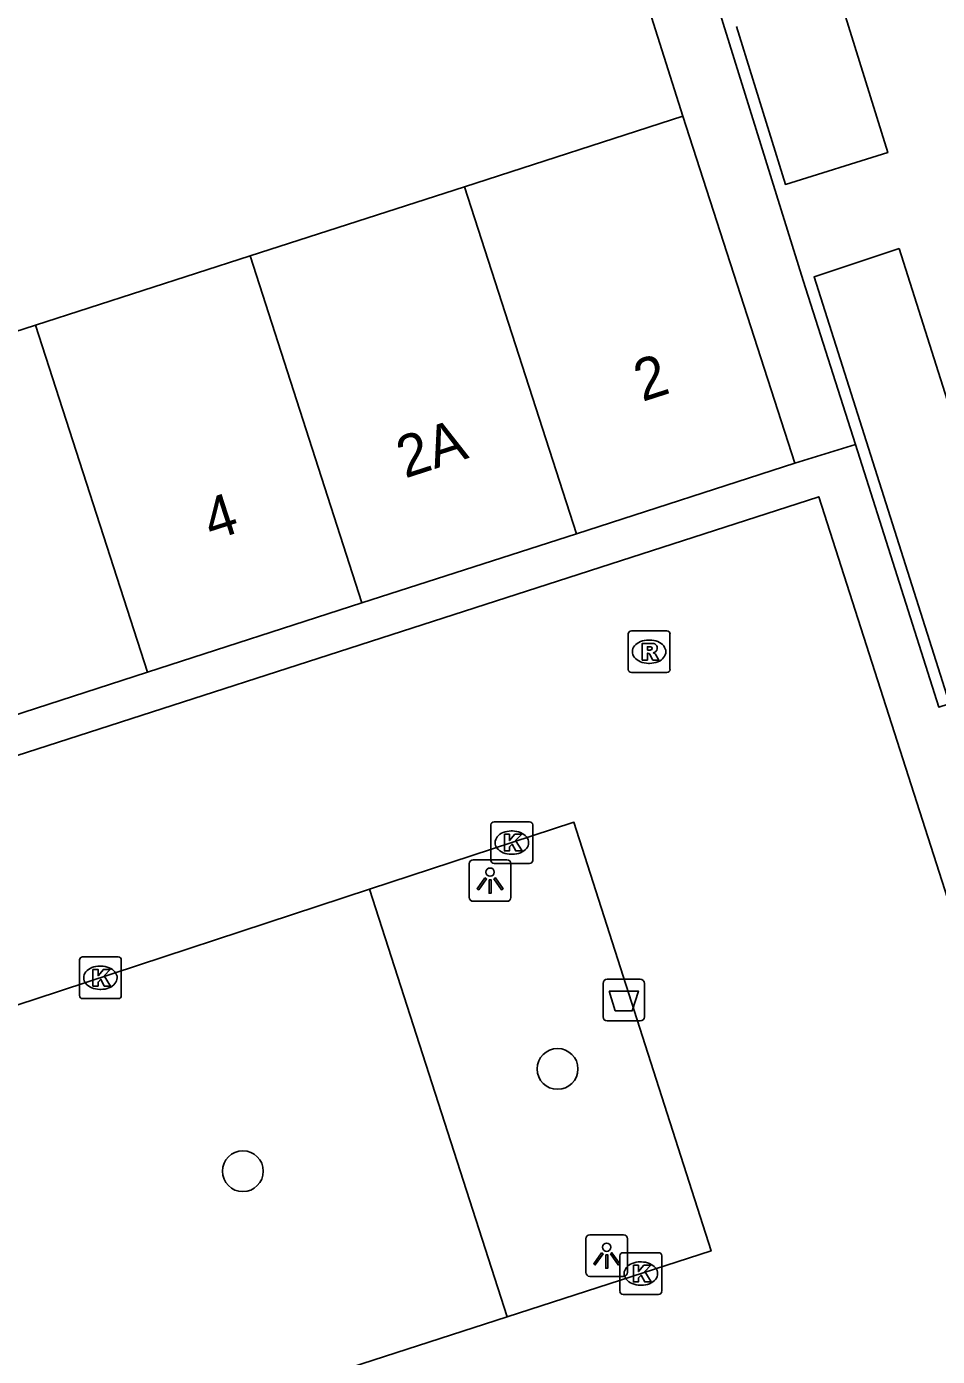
# Model space of a CAD drawing. Extents: x 159377 to 159983, y 382996 to 383595.
# Drawn here: x 159683.95 to 159705.78, y 383204.43 to 383236.31 of the extents above; entities that cross this region are included whole.
import ezdxf

# ---------------------------------------------------------------- set-up
doc = ezdxf.new("R2010")
doc.units = 0
for name, color, linetype in [('IMGEO_Afvalbak', 7, 'Continuous'), ('IMGEO_Boom', 7, 'Continuous'), ('IMGEO_Kolk', 7, 'Continuous'), ('IMGEO_Lichtpunt', 7, 'Continuous'), ('IMGEO_Pand', 7, 'Continuous'), ('IMGEO_Pand_nummerreeks', 7, 'Continuous'), ('IMGEO_Rijbaan_lokaal_open', 7, 'Continuous'), ('IMGEO_Rioolput', 7, 'Continuous'), ('IMGEO_Voetpad_open', 7, 'Continuous')]:
    doc.layers.add(name, color=color, linetype=linetype)

msp = doc.modelspace()

# ---------------------------------------------------------------- linework, layer by layer
at = {"layer": 'IMGEO_Afvalbak'}
for p, q in [((159697.768, 383212.573), (159697.768, 383213.373)), ((159697.768, 383213.373), (159697.768, 383212.573)), ((159697.868, 383213.473), (159698.658, 383213.473)), ((159698.658, 383213.473), (159697.868, 383213.473)), ((159698.758, 383213.373), (159698.758, 383212.573)), ((159698.758, 383212.573), (159698.758, 383213.373)), ((159698.658, 383212.473), (159697.868, 383212.473)), ((159697.868, 383212.473), (159698.658, 383212.473))]:
    msp.add_line(p, q, dxfattribs=at)
msp.add_lwpolyline([(159697.911, 383213.187), (159698.615, 383213.187), (159698.466, 383212.717), (159698.06, 383212.717), (159697.911, 383213.187)], dxfattribs=at)
for centre, start, end in [((159697.868, 383213.373), 90, 180), ((159697.868, 383213.373), 90, 180), ((159698.658, 383213.373), 0, 90), ((159698.658, 383213.373), 360, 90), ((159697.868, 383212.573), 180, 270), ((159697.868, 383212.573), 180, 270), ((159698.658, 383212.573), 270, 0), ((159698.658, 383212.573), 270, 0)]:
    msp.add_arc(centre, 0.1, start, end, dxfattribs=at)
at = {"layer": 'IMGEO_Boom'}
for centre in [(159696.677, 383211.322), (159689.133, 383208.87)]:
    msp.add_circle(centre, 0.489, dxfattribs=at)
at = {"layer": 'IMGEO_Kolk'}
for p, q in [((159695.08, 383216.322), (159695.08, 383217.174)), ((159695.155, 383217.248), (159696.007, 383217.248)), ((159696.081, 383217.174), (159696.081, 383216.322)), ((159695.568, 383217.028), (159695.593, 383217.028)), ((159695.591, 383216.468), (159695.566, 383216.468)), ((159696.007, 383216.248), (159695.155, 383216.248)), ((159685.216, 383213.082), (159685.216, 383213.934)), ((159685.291, 383214.008), (159686.143, 383214.008)), ((159686.217, 383213.934), (159686.217, 383213.082)), ((159685.704, 383213.788), (159685.729, 383213.788)), ((159686.143, 383213.008), (159685.291, 383213.008)), ((159685.727, 383213.228), (159685.702, 383213.228)), ((159698.248, 383206.916), (159699.1, 383206.916)), ((159698.173, 383205.99), (159698.173, 383206.842)), ((159698.661, 383206.696), (159698.686, 383206.696)), ((159699.174, 383206.842), (159699.174, 383205.99)), ((159699.1, 383205.916), (159698.248, 383205.916)), ((159698.684, 383206.136), (159698.659, 383206.136))]:
    msp.add_line(p, q, dxfattribs=at)
for points in [[(159695.08, 383216.322), (159695.08, 383217.174)], [(159695.155, 383217.248), (159696.007, 383217.248)], [(159696.081, 383217.174), (159696.081, 383216.322)], [(159695.401, 383216.948), (159695.524, 383216.948), (159695.524, 383216.797), (159695.654, 383216.948), (159695.818, 383216.948), (159695.672, 383216.797), (159695.825, 383216.548), (159695.673, 383216.548), (159695.588, 383216.712), (159695.524, 383216.645), (159695.524, 383216.548), (159695.401, 383216.548), (159695.401, 383216.948)], [(159696.007, 383216.248), (159695.155, 383216.248)], [(159685.216, 383213.082), (159685.216, 383213.934)], [(159685.291, 383214.008), (159686.143, 383214.008)], [(159686.217, 383213.934), (159686.217, 383213.082)], [(159685.537, 383213.708), (159685.66, 383213.708), (159685.66, 383213.557), (159685.79, 383213.708), (159685.954, 383213.708), (159685.808, 383213.557), (159685.961, 383213.308), (159685.809, 383213.308), (159685.724, 383213.472), (159685.66, 383213.405), (159685.66, 383213.308), (159685.537, 383213.308), (159685.537, 383213.708)], [(159686.143, 383213.008), (159685.291, 383213.008)], [(159698.248, 383206.916), (159699.1, 383206.916)], [(159698.173, 383205.99), (159698.173, 383206.842)], [(159698.494, 383206.616), (159698.617, 383206.616), (159698.617, 383206.465), (159698.747, 383206.616), (159698.911, 383206.616), (159698.765, 383206.465), (159698.918, 383206.216), (159698.766, 383206.216), (159698.681, 383206.38), (159698.617, 383206.313), (159698.617, 383206.216), (159698.494, 383206.216), (159698.494, 383206.616)], [(159699.174, 383206.842), (159699.174, 383205.99)], [(159699.1, 383205.916), (159698.248, 383205.916)]]:
    msp.add_lwpolyline(points, dxfattribs=at)
for centre, start, end in [((159695.157, 383217.172), 91.552, 178.448), ((159695.157, 383217.172), 91.552, 178.448), ((159696.005, 383217.172), 1.552, 88.448), ((159696.005, 383217.172), 1.552, 88.448), ((159695.157, 383216.324), 181.552, 268.448), ((159695.157, 383216.324), 181.552, 268.448), ((159696.005, 383216.324), 271.552, 358.448), ((159696.005, 383216.324), 271.552, 358.448), ((159685.293, 383213.932), 91.552, 178.448), ((159685.293, 383213.932), 91.552, 178.448), ((159686.141, 383213.932), 1.552, 88.448), ((159686.141, 383213.932), 1.552, 88.448), ((159685.293, 383213.084), 181.552, 268.448), ((159685.293, 383213.084), 181.552, 268.448), ((159686.141, 383213.084), 271.552, 358.448), ((159686.141, 383213.084), 271.552, 358.448), ((159698.25, 383206.84), 91.552, 178.448), ((159698.25, 383206.84), 91.552, 178.448), ((159699.098, 383206.84), 1.552, 88.448), ((159699.098, 383206.84), 1.552, 88.448), ((159698.25, 383205.992), 181.552, 268.448), ((159698.25, 383205.992), 181.552, 268.448), ((159699.098, 383205.992), 271.552, 358.448), ((159699.098, 383205.992), 271.552, 358.448)]:
    msp.add_arc(centre, 0.0765, start, end, dxfattribs=at)
for centre, major_axis, ratio, start_param, end_param in [((159695.567, 383216.748), (-0.387, 0.002), 0.722429, 4.712389, 7.853982), ((159695.592, 383216.748), (-0.39, 0.002), 0.717154, 1.570796, 4.712389), ((159685.703, 383213.508), (-0.387, 0.002), 0.722429, 4.712389, 7.853982), ((159685.728, 383213.508), (-0.39, 0.002), 0.717154, 1.570796, 4.712389), ((159698.66, 383206.416), (-0.387, 0.002), 0.722429, 4.712389, 7.853982), ((159698.685, 383206.416), (-0.39, 0.002), 0.717154, 1.570796, 4.712389)]:
    msp.add_ellipse(centre, major_axis=major_axis, ratio=ratio, start_param=start_param, end_param=end_param, dxfattribs=at)
at = {"layer": 'IMGEO_Lichtpunt'}
for p, q in [((159694.561, 383216.242), (159694.561, 383215.435)), ((159694.561, 383216.242), (159694.561, 383215.435)), ((159695.463, 383216.337), (159694.655, 383216.337)), ((159695.463, 383216.337), (159694.655, 383216.337)), ((159695.557, 383215.435), (159695.557, 383216.242)), ((159695.557, 383215.435), (159695.557, 383216.242)), ((159694.655, 383215.341), (159695.463, 383215.341)), ((159694.655, 383215.341), (159695.463, 383215.341)), ((159697.356, 383207.25), (159697.356, 383206.443)), ((159697.356, 383207.25), (159697.356, 383206.443)), ((159698.258, 383207.345), (159697.45, 383207.345)), ((159698.258, 383207.345), (159697.45, 383207.345)), ((159698.352, 383206.443), (159698.352, 383207.25)), ((159698.352, 383206.443), (159698.352, 383207.25)), ((159697.45, 383206.349), (159698.258, 383206.349)), ((159697.45, 383206.349), (159698.258, 383206.349))]:
    msp.add_line(p, q, dxfattribs=at)
for points in [[(159694.935, 383215.906), (159694.974, 383215.878), (159694.786, 383215.616), (159694.748, 383215.643), (159694.935, 383215.906)], [(159695.037, 383215.858), (159695.084, 383215.858), (159695.084, 383215.536), (159695.037, 383215.536), (159695.037, 383215.858)], [(159695.147, 383215.878), (159695.185, 383215.905), (159695.372, 383215.643), (159695.333, 383215.615), (159695.147, 383215.878)], [(159697.73, 383206.914), (159697.769, 383206.886), (159697.581, 383206.624), (159697.543, 383206.651), (159697.73, 383206.914)], [(159697.942, 383206.886), (159697.98, 383206.913), (159698.167, 383206.651), (159698.128, 383206.623), (159697.942, 383206.886)], [(159697.832, 383206.866), (159697.879, 383206.866), (159697.879, 383206.544), (159697.832, 383206.544), (159697.832, 383206.866)]]:
    msp.add_lwpolyline(points, dxfattribs=at)
for centre in [(159695.06, 383216.04), (159697.855, 383207.048)]:
    msp.add_circle(centre, 0.0994, dxfattribs=at)
for centre, start, end in [((159694.655, 383216.242), 90, 180), ((159694.655, 383216.242), 90, 180), ((159695.463, 383216.242), 0, 90), ((159695.463, 383216.242), 0, 90), ((159694.655, 383215.435), 180, 270), ((159694.655, 383215.435), 180, 270), ((159695.463, 383215.435), 270, 0), ((159695.463, 383215.435), 270, 360), ((159697.45, 383207.25), 90, 180), ((159697.45, 383207.25), 90, 180), ((159698.258, 383207.25), 0, 90), ((159698.258, 383207.25), 0, 90), ((159697.45, 383206.443), 180, 270), ((159697.45, 383206.443), 180, 270), ((159698.258, 383206.443), 270, 0), ((159698.258, 383206.443), 270, 360)]:
    msp.add_arc(centre, 0.0946, start, end, dxfattribs=at)
at = {"layer": 'IMGEO_Pand'}
for points in [[(159703.388, 383237.179), (159704.594, 383233.291), (159702.139, 383232.53), (159700.963, 383236.318)], [(159699.678, 383234.162), (159694.444, 383232.473)], [(159702.363, 383225.842), (159699.678, 383234.162)], [(159694.444, 383232.473), (159689.304, 383230.813)], [(159694.444, 383232.473), (159697.129, 383224.153)], [(159689.304, 383230.813), (159684.163, 383229.154)], [(159689.304, 383230.813), (159691.988, 383222.493)], [(159704.866, 383230.994), (159708.058, 383220.936), (159706.01, 383220.281), (159702.826, 383230.313), (159704.866, 383230.994)], [(159678.732, 383227.401), (159684.163, 383229.154)], [(159684.163, 383229.154), (159686.848, 383220.834)], [(159697.129, 383224.153), (159702.363, 383225.842)], [(159691.988, 383222.493), (159697.129, 383224.153)], [(159686.848, 383220.834), (159691.988, 383222.493)], [(159686.848, 383220.834), (159681.488, 383219.104)]]:
    msp.add_lwpolyline(points, dxfattribs=at)
at = {"layer": 'IMGEO_Rijbaan_lokaal_open'}
for points in [[(159718.043, 383217.834), (159716.104, 383216.99), (159706.635, 383213.525), (159702.938, 383225.039), (159675.192, 383216.084), (159669.539, 383233.494)], [(159692.168, 383215.628), (159697.07, 383217.238), (159700.356, 383206.959), (159695.472, 383205.38)], [(159670.044, 383208.389), (159684.151, 383212.994), (159692.168, 383215.628)], [(159695.472, 383205.38), (159673.271, 383198.205)]]:
    msp.add_lwpolyline(points, dxfattribs=at)
at = {"layer": 'IMGEO_Rioolput'}
for p, q in [((159698.371, 383220.899), (159698.371, 383221.751)), ((159698.446, 383221.825), (159699.298, 383221.825)), ((159698.859, 383221.605), (159698.884, 383221.605)), ((159699.372, 383221.751), (159699.372, 383220.899)), ((159698.882, 383221.045), (159698.857, 383221.045)), ((159699.298, 383220.825), (159698.446, 383220.825))]:
    msp.add_line(p, q, dxfattribs=at)
for points in [[(159698.371, 383220.899), (159698.371, 383221.751)], [(159698.446, 383221.825), (159699.298, 383221.825)], [(159699.372, 383221.751), (159699.372, 383220.899)], [(159698.96, 383221.523), (159698.708, 383221.525), (159698.708, 383221.125)], [(159698.708, 383221.125), (159698.832, 383221.125), (159698.832, 383221.287), (159698.843, 383221.287)], [(159698.886, 383221.444), (159698.832, 383221.444), (159698.832, 383221.363)], [(159698.832, 383221.363), (159698.884, 383221.363)], [(159698.89, 383221.258), (159698.961, 383221.125), (159699.101, 383221.125), (159699.036, 383221.251)], [(159699.298, 383220.825), (159698.446, 383220.825)]]:
    msp.add_lwpolyline(points, dxfattribs=at)
for centre, radius, start, end in [((159698.448, 383221.749), 0.0765, 91.552, 178.448), ((159698.448, 383221.749), 0.0765, 91.552, 178.448), ((159699.296, 383221.749), 0.0765, 1.552, 88.448), ((159699.296, 383221.749), 0.0765, 1.552, 88.448), ((159698.842, 383221.234), 0.0533, 26.0293, 88.6989), ((159698.868, 383221.552), 0.19, 274.7715, 282.9687), ((159698.892, 383221.348), 0.0964, 77.0061, 93.1865), ((159698.906, 383221.405), 0.0378, 276.6634, 79.6772), ((159698.959, 383221.413), 0.109, 350.3612, 89.416), ((159698.957, 383221.413), 0.112, 277.5842, 350.9817), ((159698.941, 383221.198), 0.108, 29.5134, 73.7905), ((159698.448, 383220.901), 0.0765, 181.552, 268.448), ((159698.448, 383220.901), 0.0765, 181.552, 268.448), ((159699.296, 383220.901), 0.0765, 271.552, 358.448), ((159699.296, 383220.901), 0.0765, 271.552, 358.448)]:
    msp.add_arc(centre, radius, start, end, dxfattribs=at)
for centre, major_axis, ratio, start_param, end_param in [((159698.858, 383221.325), (-0.387, 0.002), 0.722429, 4.712389, 7.853982), ((159698.883, 383221.325), (-0.39, 0.002), 0.717154, 1.570796, 4.712389)]:
    msp.add_ellipse(centre, major_axis=major_axis, ratio=ratio, start_param=start_param, end_param=end_param, dxfattribs=at)
at = {"layer": 'IMGEO_Voetpad_open'}
for points in [[(159695.365, 383253.117), (159695.59, 383252.391), (159696.512, 383249.693), (159697.469, 383246.61), (159698.877, 383242.072), (159702.568, 383230.227), (159703.816, 383226.296)], [(159697.021, 383242.578), (159699.678, 383234.162)], [(159702.363, 383225.842), (159703.816, 383226.296)], [(159703.816, 383226.296), (159705.815, 383219.996), (159706.268, 383220.141)], [(159695.472, 383205.38), (159692.168, 383215.628)]]:
    msp.add_lwpolyline(points, dxfattribs=at)

# ---------------------------------------------------------------- texts
at = {"layer": 'IMGEO_Pand_nummerreeks'}
for s, p in [('2', (159698.708, 383227.311)), ('2A', (159693.02, 383225.475)), ('4', (159688.382, 383223.978))]:
    msp.add_text(s, height=1, rotation=17.8878, dxfattribs=at).set_placement(p)

doc.saveas('drawing.dxf')
